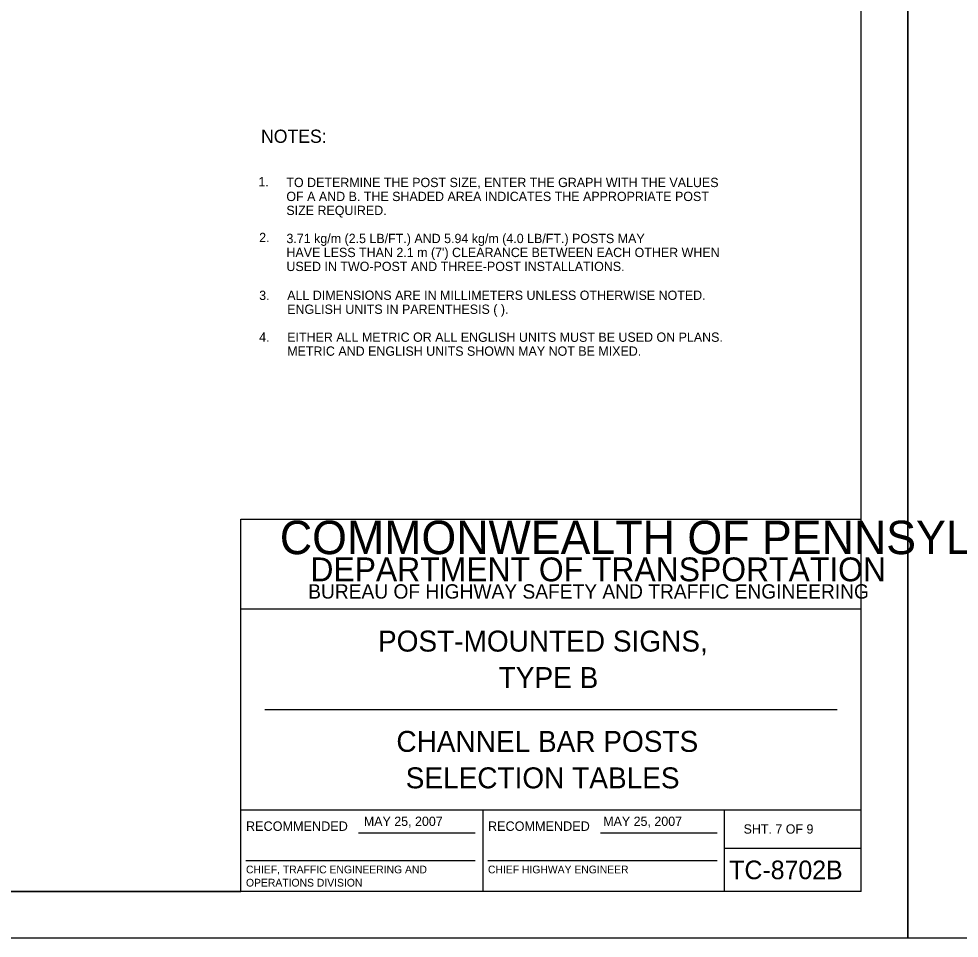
# Model space of a CAD drawing. Extents: x 644358 to 648627, y 294594 to 295782.
# Drawn here: x 645753.8 to 646056.9, y 294593.6 to 294889.9 of the extents above; entities that cross this region are included whole.
import ezdxf

# ---------------------------------------------------------------- set-up
doc = ezdxf.new("R2010")
doc.units = 0
for name, color, linetype in [('1', 7, 'Continuous'), ('2', 7, 'Continuous'), ('3', 7, 'Continuous'), ('4', 7, 'Continuous'), ('PLT-BNDY', 7, 'Continuous')]:
    doc.layers.add(name, color=color, linetype=linetype)

msp = doc.modelspace()

# ---------------------------------------------------------------- linework, layer by layer
at = {"layer": '1'}
for p, q in [((646025.31, 294608.63), (646025.31, 295172.63)), ((645825.31, 294608.63), (645825.31, 294728.63)), ((645825.31, 294728.63), (646025.31, 294728.63)), ((646025.31, 294699.63), (645825.31, 294699.63)), ((645833.06, 294667.31), (646017.56, 294667.31)), ((645825.31, 294635), (646025.31, 294635)), ((645903.31, 294635), (645903.31, 294608.63)), ((645981.19, 294608.63), (645981.19, 294635)), ((645863.24, 294627.57), (645900.87, 294627.57)), ((645941.24, 294627.57), (645978.87, 294627.57)), ((645981.19, 294622.63), (646025.31, 294622.63)), ((645826.99, 294618.68), (645900.87, 294618.68)), ((645904.99, 294618.68), (645978.87, 294618.68)), ((646025.31, 294608.63), (645239.31, 294608.63)), ((645239.31, 294608.63), (645825.31, 294608.63))]:
    msp.add_line(p, q, dxfattribs=at)
at = {"layer": 'PLT-BNDY'}
for points in [[(645199.31, 295187.63), (646040.31, 295187.63), (646040.31, 294593.63), (645199.31, 294593.63)], [(646040.31, 295187.63), (646881.31, 295187.63), (646881.31, 294593.63), (646040.31, 294593.63)]]:
    msp.add_lwpolyline(points, close=True, dxfattribs=at)

# ---------------------------------------------------------------- texts
at = {"layer": '1'}
for s, height, p in [('COMMONWEALTH OF PENNSYLVANIA', 10.7828, (645837.9, 294717.36)), ('DEPARTMENT OF TRANSPORTATION', 7.6837, (645847.76, 294708.61)), ('BUREAU OF HIGHWAY SAFETY AND TRAFFIC ENGINEERING', 4.6253, (645847.04, 294703.04)), ('POST-MOUNTED SIGNS,', 6.75, (645869.54, 294685.97)), ('TYPE B', 6.75, (645908.45, 294674.22)), ('CHANNEL BAR POSTS', 6.75, (645875.47, 294653.66)), ('SELECTION TABLES', 6.75, (645878.47, 294641.91)), ('RECOMMENDED', 3.048, (645826.99, 294628.2)), ('RECOMMENDED', 3.048, (645904.99, 294628.2)), ('SHT. 7 OF 9', 3, (645987.39, 294627.31)), ('CHIEF, TRAFFIC ENGINEERING AND', 2.5, (645826.99, 294614.51)), ('CHIEF HIGHWAY ENGINEER', 2.5, (645904.99, 294614.51)), ('TC-8702B', 6, (645982.77, 294612.63)), ('OPERATIONS DIVISION', 2.5, (645826.99, 294610.26))]:
    msp.add_text(s, height=height, dxfattribs=at).set_placement(p)
at = {"layer": '2'}
for p in [(645864.98, 294629.79), (645942.14, 294629.79)]:
    msp.add_text('MAY 25, 2007', height=3, dxfattribs=at).set_placement(p)
at = {"layer": '3'}
for s, p in [('1.', (645830.99, 294835.83)), ('TO DETERMINE THE POST SIZE, ENTER THE GRAPH WITH THE VALUES', (645840.01, 294835.63)), ('OF A AND B. THE SHADED AREA INDICATES THE APPROPRIATE POST', (645840.01, 294831.13)), ('SIZE REQUIRED.', (645840.01, 294826.63)), ('2.', (645831.24, 294817.89)), ('3.71 kg/m (2.5 LB/FT.) AND 5.94 kg/m (4.0 LB/FT.) POSTS MAY ', (645840.03, 294817.58)), ("HAVE LESS THAN 2.1 m (7') CLEARANCE BETWEEN EACH OTHER WHEN ", (645840.03, 294813.08)), ('USED IN TWO-POST AND THREE-POST INSTALLATIONS.', (645840.03, 294808.58)), ('3.', (645831.24, 294799.24)), ('4.', (645831.24, 294785.8))]:
    msp.add_text(s, height=3, dxfattribs=at).set_placement(p)
at = {"layer": '4'}
for s, height, p in [('NOTES:', 4.25, (645831.84, 294849.89)), ('ALL DIMENSIONS ARE IN MILLIMETERS UNLESS OTHERWISE NOTED.', 3, (645840.28, 294799.28)), ('ENGLISH UNITS IN PARENTHESIS ( ).', 3, (645840.28, 294794.78)), ('EITHER ALL METRIC OR ALL ENGLISH UNITS MUST BE USED ON PLANS.', 3, (645840.28, 294785.78)), ('METRIC AND ENGLISH UNITS SHOWN MAY NOT BE MIXED.', 3, (645840.28, 294781.28))]:
    msp.add_text(s, height=height, dxfattribs=at).set_placement(p)

doc.saveas('drawing.dxf')
